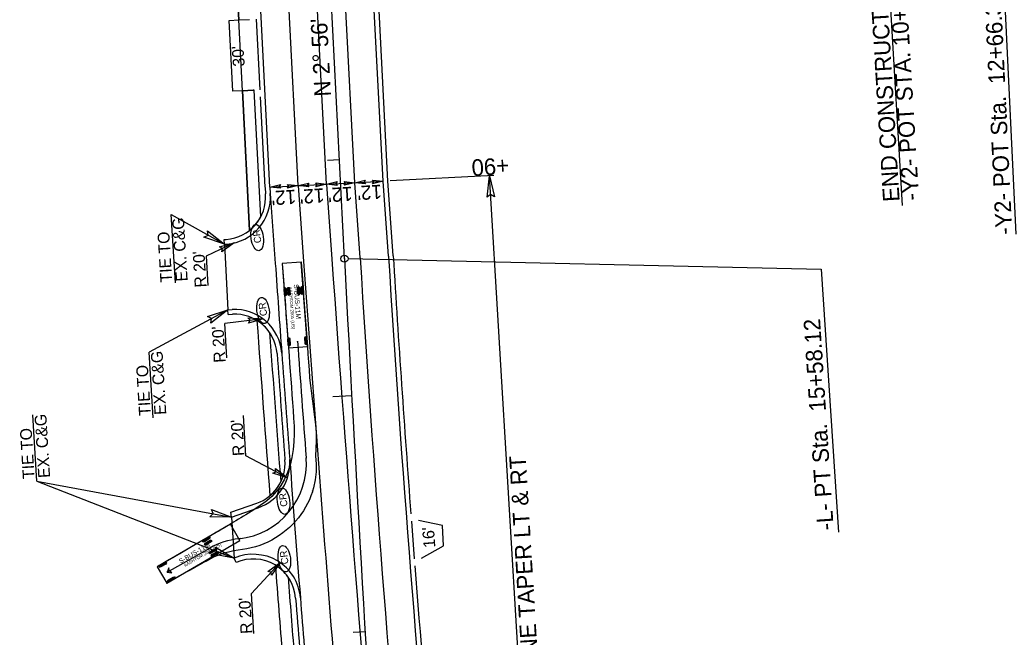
# Model space of a CAD drawing. Extents: x 2367848 to 2369479, y 800728 to 808616.
# Drawn here: x 2368791.8 to 2369213.4, y 801728.3 to 801989.4 of the extents above; entities that cross this region are included whole.
import ezdxf

# ---------------------------------------------------------------- set-up
doc = ezdxf.new("R2010")
doc.units = 0
for name, color, linetype in [('Prop AutoTurn Projected Path', 7, 'Continuous'), ('Prop Conc 2ft 6in Curb and Gutter', 7, 'Continuous'), ('Prop Conc 4in Sidewalk', 7, 'Continuous'), ('Prop Conc Drive Radius Type', 7, 'Continuous'), ('Prop Conc Driveway', 7, 'Continuous'), ('Prop Dimension', 7, 'Continuous'), ('Prop EOT', 7, 'Continuous'), ('Prop Horizontal Alignment', 7, 'Continuous'), ('Prop Horizontal Alignment Direction Label', 7, 'Continuous'), ('Prop Horizontal Alignment Station Label', 7, 'Continuous'), ('Prop Horizontal Alignment Tick Large', 7, 'Continuous'), ('Prop Horizontal Alignment Tick Small', 7, 'Continuous'), ('Prop Lane Lines', 7, 'Continuous'), ('Prop Shade Light', 7, 'Continuous'), ('Prop Terminator CELL', 7, 'Continuous'), ('Prop WCC CELL', 7, 'Continuous'), ('Prop WCR CELL', 7, 'Continuous')]:
    doc.layers.add(name, color=color, linetype=linetype)

# ---------------------------------------------------------------- blocks, each defined once
blk = doc.blocks.new('CR')
at = {"layer": 'Prop WCC CELL'}
blk.add_ellipse((0.02, -0.02), major_axis=(5.61, 0), ratio=0.462467, dxfattribs=at)
blk.add_text('CR', height=3, dxfattribs=at).set_placement((-2.34, -1.5))

msp = doc.modelspace()

# ---------------------------------------------------------------- linework, layer by layer
at = {"layer": 'Prop AutoTurn Projected Path'}
for p, q in [((2368910.84, 801886.97), (2368902.86, 801886.38)), ((2368902.86, 801886.38), (2368905.47, 801850.69)), ((2368913.45, 801851.27), (2368910.84, 801886.97)), ((2368904.06, 801872.76), (2368903.82, 801876.09)), ((2368904.27, 801872.78), (2368904.03, 801876.1)), ((2368904.48, 801872.79), (2368904.23, 801876.12)), ((2368905.56, 801872.87), (2368905.32, 801876.2)), ((2368905.77, 801872.89), (2368905.52, 801876.21)), ((2368905.97, 801872.9), (2368905.73, 801876.23)), ((2368909.72, 801873.17), (2368909.48, 801876.5)), ((2368909.93, 801873.19), (2368909.68, 801876.51)), ((2368910.13, 801873.21), (2368909.89, 801876.53)), ((2368911.22, 801873.28), (2368910.97, 801876.61)), ((2368911.42, 801873.3), (2368911.18, 801876.62)), ((2368911.63, 801873.31), (2368911.39, 801876.64)), ((2368905.61, 801851.53), (2368905.37, 801854.85)), ((2368905.82, 801851.54), (2368905.58, 801854.87)), ((2368906.03, 801851.56), (2368905.79, 801854.88)), ((2368912.77, 801852.05), (2368912.52, 801855.37)), ((2368912.98, 801852.06), (2368912.73, 801855.39)), ((2368913.18, 801852.08), (2368912.94, 801855.4)), ((2368905.47, 801850.69), (2368913.45, 801851.27)), ((2368913.45, 801851.27), (2368913.45, 801851.27)), ((2368880.87, 801776), (2368849.92, 801758.01)), ((2368884.89, 801769.08), (2368880.87, 801776)), ((2368869.15, 801768.95), (2368872.03, 801770.62)), ((2368869.25, 801768.77), (2368872.14, 801770.44)), ((2368869.36, 801768.59), (2368872.24, 801770.26)), ((2368869.9, 801767.65), (2368872.78, 801769.33)), ((2368885.29, 801769.96), (2368884.28, 801769.83)), ((2368853.95, 801751.09), (2368884.89, 801769.08)), ((2368854.09, 801755.8), (2368872.22, 801765.96)), ((2368870.01, 801767.47), (2368872.89, 801769.15)), ((2368870.11, 801767.29), (2368872.99, 801768.97)), ((2368872, 801764.05), (2368874.88, 801765.72)), ((2368872.11, 801763.87), (2368874.99, 801765.54)), ((2368872.21, 801763.69), (2368875.09, 801765.36)), ((2368872.75, 801762.75), (2368875.64, 801764.42)), ((2368872.86, 801762.57), (2368875.74, 801764.24)), ((2368872.96, 801762.39), (2368875.85, 801764.06)), ((2368849.92, 801758.01), (2368853.95, 801751.09)), ((2368850.74, 801758.27), (2368853.65, 801759.9)), ((2368850.84, 801758.09), (2368853.75, 801759.72)), ((2368850.94, 801757.91), (2368853.85, 801759.54)), ((2368854.33, 801752.07), (2368857.24, 801753.7)), ((2368854.43, 801751.88), (2368857.34, 801753.51)), ((2368854.54, 801751.7), (2368857.44, 801753.33)), ((2368853.95, 801751.09), (2368853.95, 801751.09))]:
    msp.add_line(p, q, dxfattribs=at)
for points in [[(2368902.86, 801886.38), (2368903.12, 801882.81), (2368903.38, 801879.24), (2368903.64, 801875.67), (2368903.9, 801872.1), (2368904.16, 801868.53), (2368904.42, 801864.97), (2368904.68, 801861.4), (2368904.94, 801857.83), (2368905.21, 801854.26), (2368905.47, 801850.69), (2368905.47, 801850.69), (2368905.47, 801850.69), (2368905.71, 801847.37), (2368905.95, 801844.06), (2368906.2, 801840.74), (2368906.44, 801837.43), (2368906.69, 801834.11), (2368906.93, 801830.8), (2368907.18, 801827.49), (2368907.42, 801824.17), (2368907.66, 801820.86), (2368907.83, 801817.54), (2368907.88, 801814.22), (2368907.78, 801810.9), (2368907.48, 801807.59), (2368906.95, 801804.31), (2368906.16, 801801.08), (2368905.1, 801797.98), (2368903.77, 801795.07), (2368902.2, 801792.39), (2368901.51, 801791.39)], [(2368910.84, 801886.97), (2368911.1, 801883.4), (2368911.36, 801879.83), (2368911.62, 801876.26), (2368911.89, 801872.69), (2368912.15, 801869.12), (2368912.41, 801865.55), (2368912.67, 801861.98), (2368912.93, 801858.41), (2368913.19, 801854.84), (2368913.46, 801851.27), (2368913.46, 801851.27), (2368913.7, 801847.96), (2368913.94, 801844.64), (2368914.19, 801841.33), (2368914.43, 801838.01), (2368914.73, 801834.7), (2368915.15, 801831.4), (2368915.63, 801828.09), (2368916.12, 801824.77), (2368916.55, 801821.42), (2368916.9, 801818.06), (2368917.12, 801814.68), (2368917.18, 801811.33), (2368917.01, 801808.08), (2368916.9, 801804.88), (2368917.15, 801801.57), (2368917.17, 801798.2), (2368916.82, 801794.8), (2368916.09, 801791.39), (2368915.7, 801790.05)], [(2368901.51, 801791.39), (2368901.33, 801791.15), (2368900.41, 801789.97), (2368899.44, 801788.87), (2368898.43, 801787.83), (2368897.38, 801786.86), (2368896.29, 801785.96), (2368895.19, 801785.12), (2368894.08, 801784.32), (2368892.96, 801783.56), (2368891.85, 801782.82), (2368890.74, 801782.11), (2368889.64, 801781.42), (2368888.54, 801780.74), (2368887.46, 801780.07), (2368886.38, 801779.41), (2368885.32, 801778.76), (2368884.26, 801778.12), (2368883.21, 801777.48), (2368882.17, 801776.86), (2368881.13, 801776.24), (2368880.11, 801775.62), (2368879.09, 801775.02), (2368878.07, 801774.42), (2368877.05, 801773.81), (2368875.94, 801773.16), (2368874.76, 801772.46), (2368873.51, 801771.73), (2368872.2, 801770.97), (2368870.86, 801770.18), (2368869.48, 801769.38), (2368868.07, 801768.56), (2368866.64, 801767.73), (2368865.2, 801766.89), (2368863.76, 801766.06), (2368862.32, 801765.22), (2368860.88, 801764.38), (2368859.44, 801763.55), (2368858, 801762.71), (2368856.56, 801761.87), (2368855.12, 801761.03), (2368853.68, 801760.19), (2368852.23, 801759.35), (2368850.79, 801758.51), (2368849.92, 801758.01)], [(2368915.7, 801790.05), (2368915.59, 801789.71), (2368915, 801788.04), (2368914.32, 801786.4), (2368913.55, 801784.78), (2368912.7, 801783.2), (2368911.76, 801781.65), (2368910.75, 801780.15), (2368909.65, 801778.7), (2368908.48, 801777.3), (2368907.23, 801775.96), (2368905.91, 801774.68), (2368904.53, 801773.46), (2368903.08, 801772.32), (2368901.57, 801771.24), (2368900.01, 801770.24), (2368898.4, 801769.32), (2368896.74, 801768.49), (2368895.03, 801767.73), (2368893.29, 801767.07), (2368891.51, 801766.49), (2368889.7, 801766), (2368887.87, 801765.61), (2368886.02, 801765.31), (2368884.16, 801765.07), (2368882.35, 801764.78), (2368880.58, 801764.41), (2368878.85, 801763.97), (2368877.18, 801763.44), (2368875.56, 801762.84), (2368874, 801762.16), (2368872.49, 801761.4), (2368871.02, 801760.59), (2368869.54, 801759.77), (2368868.07, 801758.95), (2368866.59, 801758.13), (2368865.12, 801757.31), (2368863.65, 801756.49), (2368862.18, 801755.67), (2368860.71, 801754.86), (2368859.24, 801754.04), (2368857.77, 801753.22), (2368856.3, 801752.4), (2368854.83, 801751.58), (2368853.95, 801751.09)]]:
    msp.add_lwpolyline(points, dxfattribs=at)
for points in [[(2368904.53, 801872.8), (2368904.01, 801872.76), (2368903.82, 801873.21), (2368903.65, 801875.61), (2368903.77, 801876.08), (2368904.29, 801876.12), (2368904.48, 801875.67), (2368904.65, 801873.27)], [(2368906.03, 801872.9), (2368905.51, 801872.87), (2368905.32, 801873.32), (2368905.14, 801875.71), (2368905.26, 801876.19), (2368905.78, 801876.23), (2368905.97, 801875.78), (2368906.15, 801873.38)], [(2368910.19, 801873.21), (2368909.67, 801873.17), (2368909.48, 801873.63), (2368909.3, 801876.02), (2368909.42, 801876.5), (2368909.94, 801876.53), (2368910.13, 801876.08), (2368910.31, 801873.69)], [(2368911.68, 801873.32), (2368911.16, 801873.28), (2368910.97, 801873.73), (2368910.8, 801876.13), (2368910.92, 801876.61), (2368911.44, 801876.64), (2368911.63, 801876.19), (2368911.8, 801873.8)], [(2368906.08, 801851.56), (2368905.56, 801851.52), (2368905.37, 801851.98), (2368905.2, 801854.37), (2368905.32, 801854.85), (2368905.84, 801854.88), (2368906.03, 801854.43), (2368906.2, 801852.04)], [(2368913.23, 801852.08), (2368912.72, 801852.04), (2368912.53, 801852.5), (2368912.35, 801854.89), (2368912.47, 801855.37), (2368912.99, 801855.41), (2368913.18, 801854.95), (2368913.36, 801852.56)], [(2368869.38, 801768.54), (2368869.12, 801768.99), (2368869.45, 801769.36), (2368871.52, 801770.57), (2368872, 801770.67), (2368872.27, 801770.22), (2368871.94, 801769.85), (2368869.87, 801768.64)], [(2368870.14, 801767.25), (2368869.88, 801767.7), (2368870.2, 801768.07), (2368872.28, 801769.27), (2368872.76, 801769.37), (2368873.02, 801768.92), (2368872.7, 801768.55), (2368870.62, 801767.35)], [(2368872.24, 801763.64), (2368871.97, 801764.09), (2368872.3, 801764.46), (2368874.37, 801765.67), (2368874.86, 801765.77), (2368875.12, 801765.32), (2368874.79, 801764.95), (2368872.72, 801763.74)], [(2368872.99, 801762.34), (2368872.73, 801762.79), (2368873.05, 801763.16), (2368875.13, 801764.37), (2368875.61, 801764.47), (2368875.87, 801764.02), (2368875.55, 801763.65), (2368873.47, 801762.44)], [(2368850.97, 801757.86), (2368850.71, 801758.32), (2368851.04, 801758.68), (2368853.14, 801759.86), (2368853.62, 801759.95), (2368853.88, 801759.49), (2368853.54, 801759.13), (2368851.45, 801757.96)], [(2368854.09, 801755.8), (2368856.07, 801755.52), (2368854.96, 801756.29), (2368854.88, 801757.64)], [(2368854.56, 801751.66), (2368854.31, 801752.11), (2368854.64, 801752.48), (2368856.73, 801753.65), (2368857.21, 801753.74), (2368857.47, 801753.29), (2368857.14, 801752.92), (2368855.04, 801751.75)]]:
    msp.add_lwpolyline(points, close=True, dxfattribs=at)
for centre in [(2368902.86, 801886.38), (2368910.84, 801886.97), (2368909.28, 801853.46), (2368912.95, 801804.09), (2368912.95, 801804.09), (2368901.51, 801791.39), (2368901.51, 801791.39), (2368915.7, 801790.05), (2368915.7, 801790.05), (2368884.45, 801769.86), (2368884.45, 801769.86), (2368872.22, 801765.96), (2368872.22, 801765.96), (2368849.92, 801758.01), (2368854.09, 801755.8), (2368853.95, 801751.09)]:
    msp.add_circle(centre, 0.0417, dxfattribs=at)
for centre, radius, start, end in [((2388872.62, 803312.97), 20016.62, 184.181412, 184.323133), ((2368881.04, 801801.68), 32, 276.1172, 4.3231), ((2368887.86, 801738.04), 32, 96.1172, 119.2606)]:
    msp.add_arc(centre, radius, start, end, dxfattribs=at)
at = {"layer": 'Prop Conc 2ft 6in Curb and Gutter'}
for p, q in [((2368947.51, 801921.27), (2368939.37, 802079.62)), ((2368895.58, 801918.6), (2368893.61, 801956.86)), ((2368949.77, 801889.63), (2368947.51, 801921.31)), ((2368895.58, 801918.56), (2368895.78, 801915.8)), ((2368878.22, 801896.49), (2368879.16, 801896.56)), ((2368878.37, 801894.5), (2368878.22, 801896.49)), ((2368879.94, 801864.82), (2368879.83, 801866.81)), ((2368879.94, 801864.82), (2368881.73, 801864.91)), ((2368881.13, 801781.06), (2368892.02, 801784.91)), ((2368881.38, 801779.03), (2368881.13, 801781.06)), ((2368883.27, 801759.78), (2368882.46, 801761.61))]:
    msp.add_line(p, q, dxfattribs=at)
for centre, radius, start, end in [((2368877.82, 801914.51), 18, 274.2541, 4.0821), ((2377170.39, 802398.06), 8236.32, 183.53925, 184.30105), ((2368882.68, 801846.94), 18, 4.1945, 93.0317), ((2388872.6, 803312.97), 20025.6, 184.19448, 184.323627), ((2368886.04, 801801.88), 18, 289.4241, 4.3236), ((2368890.55, 801743.32), 18, 4.4915, 113.8787), ((2377170.39, 802398.06), 8236.32, 184.454104, 185.074128), ((2388872.6, 803312.97), 20025.6, 184.491525, 184.551113)]:
    msp.add_arc(centre, radius, start, end, dxfattribs=at)
at = {"layer": 'Prop Conc 4in Sidewalk'}
for p, q in [((2368884.43, 801989.44), (2368883.68, 802004.04)), ((2368889, 801900.41), (2368885.97, 801959.45)), ((2368890.46, 801959.7), (2368890.46, 801959.7)), ((2368893.72, 801906.07), (2368890.96, 801959.68))]:
    msp.add_line(p, q, dxfattribs=at)
for centre, radius, start, end in [((2368890.6, 801956.7), 3.01, 83.1544, 92.6835), ((2368877.82, 801914.51), 18, 308.3943, 332.0137), ((2368882.68, 801846.94), 18, 34.7398, 58.4882), ((2388872.6, 803312.97), 20033.1, 184.152677, 184.365431), ((2388872.6, 803312.97), 20028.1, 184.16831, 184.349797), ((2368886.04, 801801.88), 18, 310.0299, 333.7783), ((2368890.55, 801743.32), 18, 35.0369, 58.7853), ((2388872.6, 803312.97), 20033.1, 184.449721, 184.559698), ((2388872.6, 803312.97), 20028.1, 184.465354, 184.559576)]:
    msp.add_arc(centre, radius, start, end, dxfattribs=at)
at = {"layer": 'Prop Conc Drive Radius Type'}
for p, q in [((2368893.46, 801959.85), (2368891.94, 801989.82)), ((2368957.48, 801777.36), (2368958.71, 801761.41))]:
    msp.add_line(p, q, dxfattribs=at)
at = {"layer": 'Prop Conc Driveway'}
for p, q in [((2368884.43, 801989.44), (2368888.94, 801989.66)), ((2368885.97, 801959.45), (2368884.43, 801989.44)), ((2368885.97, 801959.45), (2368890.46, 801959.7))]:
    msp.add_line(p, q, dxfattribs=at)
at = {"layer": 'Prop Dimension'}
for p, q in [((2369165.39, 801910.87), (2369158.52, 802024.45)), ((2368897.57, 801918.7), (2368945.51, 801921.16)), ((2368992.4, 801923.57), (2368948.46, 801921.32)), ((2369008.56, 801624.86), (2368990.51, 801923.5)), ((2368857.61, 801878.11), (2368855.86, 801907.06)), ((2368855.86, 801907.06), (2368878.37, 801894.5)), ((2368882.49, 801895.07), (2368870.6, 801889.48)), ((2368870.6, 801889.48), (2368871.35, 801877.03)), ((2368879.83, 801866.81), (2368846.48, 801848.81)), ((2368894.69, 801862.93), (2368878.5, 801860.92)), ((2368879.37, 801846.5), (2368878.5, 801860.92)), ((2368848.16, 801821.02), (2368846.48, 801848.81)), ((2368798.98, 801794.3), (2368797.3, 801822.25)), ((2368887.42, 801804.96), (2368886.39, 801822.01)), ((2368905.03, 801795.62), (2368887.42, 801804.96)), ((2368798.98, 801794.3), (2368881.38, 801779.03)), ((2368798.98, 801794.3), (2368882.46, 801761.61)), ((2368901.91, 801759.78), (2368889.77, 801746.73)), ((2368890.8, 801729.76), (2368889.77, 801746.73))]:
    msp.add_line(p, q, dxfattribs=at)
at = {"layer": 'Prop EOT'}
for p, q in [((2368945.51, 801921.16), (2368937.38, 802079.52)), ((2368897.57, 801918.7), (2368893.21, 802003.59)), ((2368880.41, 801989.24), (2368884.43, 801989.44)), ((2368881.91, 801959.23), (2368880.41, 801989.24)), ((2368885.97, 801959.45), (2368881.91, 801959.23)), ((2368947.78, 801889.49), (2368945.51, 801921.16)), ((2368897.57, 801918.7), (2368897.77, 801915.94)), ((2368878.37, 801894.5), (2368879.31, 801894.57)), ((2368878.37, 801894.5), (2368879.83, 801866.81)), ((2368879.83, 801866.81), (2368881.63, 801866.91)), ((2368881.38, 801779.03), (2368892.69, 801783.02)), ((2368881.38, 801779.03), (2368882.46, 801761.61)), ((2368970.72, 801775.52), (2368960.48, 801777.59)), ((2368971.02, 801766.92), (2368970.72, 801775.52)), ((2368961.7, 801761.64), (2368971.02, 801766.92))]:
    msp.add_line(p, q, dxfattribs=at)
for centre, radius, start, end in [((2368877.82, 801914.51), 20, 274.2541, 4.0821), ((2377170.39, 802398.06), 8238.32, 183.53925, 185.402059), ((2368882.68, 801846.94), 20, 4.1945, 93.0317), ((2388872.6, 803312.97), 20023.6, 184.19448, 184.323627), ((2368886.04, 801801.88), 20, 289.4241, 4.3236), ((2368890.55, 801743.32), 20, 4.4915, 113.8787), ((2388872.6, 803312.97), 20023.6, 184.491525, 184.609529)]:
    msp.add_arc(centre, radius, start, end, dxfattribs=at)
at = {"layer": 'Prop Horizontal Alignment'}
msp.add_line((2368929.17, 801888.4), (2368900.73, 802442.14), dxfattribs=at)
msp.add_arc((2388902.84, 802914.38), 20000, 182.940485, 183.728337, dxfattribs=at)
at = {"layer": 'Prop Horizontal Alignment Station Label'}
for p, q in [((2369213.41, 801898.71), (2369207.49, 802024.02)), ((2368930.67, 801888.48), (2369130.98, 801883.93)), ((2369130.98, 801883.93), (2369138.22, 801772.71))]:
    msp.add_line(p, q, dxfattribs=at)
msp.add_circle((2368929.17, 801888.4), 1.5, dxfattribs=at)
msp.add_circle((2368929.17, 801888.4), 1.5, dxfattribs=at)
at = {"layer": 'Prop Horizontal Alignment Tick Large'}
msp.add_line((2368932.24, 801830.36), (2368924.25, 801829.93), dxfattribs=at)
msp.add_line((2368932.24, 801830.36), (2368924.25, 801829.93), dxfattribs=at)
at = {"layer": 'Prop Horizontal Alignment Tick Small'}
for p, q in [((2368927.02, 801930.23), (2368922.03, 801929.97)), ((2368927.02, 801930.23), (2368922.03, 801929.97)), ((2368937.91, 801730.52), (2368932.91, 801730.23)), ((2368937.91, 801730.52), (2368932.91, 801730.23))]:
    msp.add_line(p, q, dxfattribs=at)
at = {"layer": 'Prop Lane Lines'}
for p, q in [((2368921.54, 801919.93), (2368894.73, 802441.83)), ((2368933.53, 801920.55), (2368906.72, 802442.44)), ((2368909.56, 801919.32), (2368902.12, 802064.13)), ((2368909.56, 801919.32), (2368911.85, 801887.27)), ((2368921.54, 801919.93), (2368923.82, 801888.13)), ((2368935.8, 801888.75), (2368933.53, 801920.55)), ((2368897.77, 801915.94), (2368899.88, 801886.42))]:
    msp.add_line(p, q, dxfattribs=at)
for centre, radius, start, end in [((2388872.62, 803312.97), 20011.62, 184.085402, 184.609529), ((2388872.62, 803312.97), 19999.62, 184.085402, 184.853798), ((2377170.39, 802398.06), 8250.32, 183.53925, 185.400841), ((2388872.6, 803312.97), 20023.6, 184.085403, 184.19448), ((2388872.6, 803312.97), 20023.6, 184.323627, 184.491525)]:
    msp.add_arc(centre, radius, start, end, dxfattribs=at)
at = {"layer": 'Prop Shade Light'}
for p, q in [((2368883.68, 802004.04), (2368884.43, 801989.44)), ((2368884.43, 801989.44), (2368888.94, 801989.66)), ((2368890.46, 801959.7), (2368885.97, 801959.45)), ((2368885.97, 801959.45), (2368889, 801900.41)), ((2368893.72, 801906.07), (2368890.96, 801959.68))]:
    msp.add_line(p, q, dxfattribs=at)
for centre, radius, start, end in [((2368890.6, 801956.7), 3.01, 83.1544, 92.6835), ((2368877.82, 801914.51), 18, 308.3943, 332.0137), ((2388872.6, 803312.97), 20033.1, 184.152677, 184.365431), ((2368882.68, 801846.94), 18, 34.7398, 58.4882), ((2388872.6, 803312.97), 20028.1, 184.16831, 184.349797), ((2368886.04, 801801.88), 18, 310.0299, 333.7783), ((2368890.55, 801743.32), 18, 35.0369, 58.7853), ((2388872.6, 803312.97), 20033.1, 184.449721, 184.559698), ((2388872.6, 803312.97), 20028.1, 184.465354, 184.559576)]:
    msp.add_arc(centre, radius, start, end, dxfattribs=at)
at = {"layer": 'Prop Terminator CELL'}
for points in [[(2368926.08, 801919.43), (2368921.54, 801919.93), (2368926.01, 801921), (2368925.48, 801920.17)], [(2368928.99, 801921.05), (2368933.53, 801920.55), (2368929.06, 801919.48), (2368929.58, 801920.31)], [(2368938.06, 801920.05), (2368933.53, 801920.55), (2368937.99, 801921.62), (2368937.47, 801920.79)], [(2368940.97, 801921.67), (2368945.51, 801921.16), (2368941.04, 801920.09), (2368941.57, 801920.93)], [(2368989.51, 801914.43), (2368990.51, 801923.5), (2368992.66, 801914.57), (2368990.99, 801915.62)], [(2368902.11, 801918.2), (2368897.57, 801918.7), (2368902.04, 801919.77), (2368901.52, 801918.94)], [(2368905.02, 801919.82), (2368909.56, 801919.32), (2368905.09, 801918.25), (2368905.62, 801919.08)], [(2368914.1, 801918.82), (2368909.56, 801919.32), (2368914.03, 801920.39), (2368913.5, 801919.56)], [(2368917, 801920.43), (2368921.54, 801919.93), (2368917.07, 801918.86), (2368917.6, 801919.69)], [(2368871.22, 801900.19), (2368878.37, 801894.5), (2368869.66, 801897.45), (2368871.44, 801898.3)], [(2368876.33, 801893.37), (2368882.49, 801895.07), (2368877.23, 801891.36), (2368877.48, 801892.71)], [(2368871.18, 801863.9), (2368879.83, 801866.81), (2368872.63, 801861.11), (2368872.88, 801863.06)], [(2368888.31, 801863.33), (2368894.69, 801862.93), (2368888.51, 801861.14), (2368889.19, 801862.34)], [(2368899.98, 801799.54), (2368905.03, 801795.62), (2368898.91, 801797.61), (2368900.15, 801798.22)], [(2368872.83, 801782.22), (2368881.38, 801779.03), (2368872.19, 801779.14), (2368873.62, 801780.5)], [(2368874.64, 801766.33), (2368882.46, 801761.61), (2368873.44, 801763.41), (2368875.1, 801764.48)], [(2368896.77, 801755.99), (2368901.91, 801759.78), (2368898.33, 801754.44), (2368898.08, 801755.79)]]:
    msp.add_lwpolyline(points, close=True, dxfattribs=at)

# ---------------------------------------------------------------- block references
at = {"layer": 'Prop WCR CELL'}
for p, rotation in [((2368892.22, 801897.3), 97.5424116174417), ((2368894.69, 801866.44), 97.5424116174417), ((2368903.33, 801785.76), 96.82125514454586), ((2368903.71, 801761.41), 97.5424116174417)]:
    msp.add_blockref('CR', p, dxfattribs=dict(at, rotation=rotation))

# ---------------------------------------------------------------- texts
at = {"layer": 'Prop AutoTurn Projected Path'}
for s, height, rotation, p in [('AASHTOM 2001 (US)', 1.3342, 274.1814, (2368905.58, 801876.45)), ('S-BUS-11M', 2.001, 274.1814, (2368907.68, 801877.54)), ('(c) 2016 Transoft Solutions, Inc. All rights reserved.', 0.0801, 274.1814, (2368908, 801870.45)), ('S-BUS-11M', 2.001, 30.1802, (2368859.79, 801759.3)), ('AASHTOM 2001 (US)', 1.3342, 30.1802, (2368861.68, 801757.89)), ('(c) 2016 Transoft Solutions, Inc. All rights reserved.', 0.0801, 30.1802, (2368866.02, 801762.69))]:
    msp.add_text(s, height=height, rotation=rotation, dxfattribs=at).set_placement(p)
at = {"layer": 'Prop Dimension'}
for s, height, rotation, p in [('-Y2- POT STA. 10+60.00', 7, 93.4586, (2369172.38, 801913.19)), ('END CONSTRUCTION', 7, 93.4586, (2369164.15, 801912.69)), ("30'", 5, 94.1086, (2368887, 801969.9)), ('+90', 7, 183.4586, (2368998.6, 801931.3)), ("12'", 6, 183.4586, (2368908.53, 801917.62)), ("12'", 6, 183.4586, (2368920.52, 801918.23)), ("12'", 6, 183.4586, (2368932.46, 801918.9)), ("12'", 6, 183.4586, (2368944.85, 801919.76)), ('EX. C&G', 5, 93.4586, (2368862.82, 801878.9)), ('TIE TO ', 5, 93.4586, (2368856.28, 801878.51)), ("R 20'", 5, 93.4586, (2368870.83, 801876.36)), ("R 20'", 5, 93.4586, (2368878.9, 801844.54)), ('EX. C&G', 5, 93.4586, (2368853.78, 801822.47)), ('TIE TO ', 5, 93.4586, (2368847.24, 801822.07)), ('EX. C&G', 5, 93.4586, (2368804.6, 801795.76)), ("R 20'", 5, 93.4586, (2368886.89, 801805.04)), ('TIE TO ', 5, 93.4586, (2368798.06, 801795.36)), ("300' LANE TAPER LT & RT", 7, 93.4586, (2369012.83, 801689.77)), ("16'", 5, 94.3857, (2368967.66, 801766.25)), ("R 20'", 5, 93.4586, (2368890.23, 801729.78))]:
    msp.add_text(s, height=height, rotation=rotation, dxfattribs=at).set_placement(p)
at = {"layer": 'Prop Horizontal Alignment Direction Label'}
msp.add_text('N 2%%d 56\' 25.7" W', height=7, rotation=92.9405, dxfattribs=at).set_placement((2368923.48, 801957.17))
at = {"layer": 'Prop Horizontal Alignment Station Label'}
for s, rotation, p in [('-Y2- POT Sta.  12+66.34', 92.7051, (2369211.82, 801898.64)), ('-L- PT Sta.  15+58.12', 93.7283, (2369136.26, 801773.66))]:
    msp.add_text(s, height=7, rotation=rotation, dxfattribs=at).set_placement(p)

doc.saveas('drawing.dxf')
